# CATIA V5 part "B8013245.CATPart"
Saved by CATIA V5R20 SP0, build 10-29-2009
Part number: B8013245
Revision: 8
Definition: design
Nomenclature: B8013245
Source: made
Description: NOT SPECIFIED
Bounding box of the stored display mesh (mm): x -28 to 28, y -28 to 28, z 0 to 45
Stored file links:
  C:\Users\Utente\Desktop\3D files B801\B8013245.CATPart
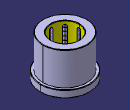
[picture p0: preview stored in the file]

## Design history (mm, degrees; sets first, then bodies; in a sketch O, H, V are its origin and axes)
Body1 "MANIFOLD_SOLID_BREP #38" (main body)
  Solid1: solid without history
Body2 "MANIFOLD_SOLID_BREP #76"
  Solid2: solid without history
Body3 "MANIFOLD_SOLID_BREP #114"
  Solid3: solid without history
Body4 "MANIFOLD_SOLID_BREP #152"
  Solid4: solid without history
Body5 "MANIFOLD_SOLID_BREP #190"
  Solid5: solid without history
Body6 "MANIFOLD_SOLID_BREP #228"
  Solid6: solid without history
Body7 "MANIFOLD_SOLID_BREP #266"
  Solid7: solid without history
Body8 "MANIFOLD_SOLID_BREP #304"
  Solid8: solid without history
Body9 "MANIFOLD_SOLID_BREP #342"
  Solid9: solid without history
Body10 "MANIFOLD_SOLID_BREP #2292"
  Solid10: solid without history
Body11 "MANIFOLD_SOLID_BREP #2330"
  Solid11: solid without history
Body12 "MANIFOLD_SOLID_BREP #2368"
  Solid12: solid without history
Body13 "MANIFOLD_SOLID_BREP #2406"
  Solid13: solid without history
Body14 "MANIFOLD_SOLID_BREP #2444"
  Solid14: solid without history
Body15 "MANIFOLD_SOLID_BREP #2482"
  Solid15: solid without history
Body16 "MANIFOLD_SOLID_BREP #2520"
  Solid16: solid without history
Body17 "MANIFOLD_SOLID_BREP #2558"
  Solid17: solid without history
Body18 "MANIFOLD_SOLID_BREP #2596"
  Solid18: solid without history
Body19 "MANIFOLD_SOLID_BREP #2634"
  Solid19: solid without history
Body20 "MANIFOLD_SOLID_BREP #2672"
  Solid20: solid without history
Body21 "MANIFOLD_SOLID_BREP #2710"
  Solid21: solid without history
Body22 "MANIFOLD_SOLID_BREP #2748"
  Solid22: solid without history
Body23 "MANIFOLD_SOLID_BREP #2786"
  Solid23: solid without history
Body24 "MANIFOLD_SOLID_BREP #2824"
  Solid24: solid without history
Body25 "MANIFOLD_SOLID_BREP #2862"
  Solid25: solid without history
Body26 "MANIFOLD_SOLID_BREP #2900"
  Solid26: solid without history
Body27 "MANIFOLD_SOLID_BREP #2938"
  Solid27: solid without history
Body28 "MANIFOLD_SOLID_BREP #2976"
  Solid28: solid without history
Body29 "MANIFOLD_SOLID_BREP #3014"
  Solid29: solid without history
Body30 "MANIFOLD_SOLID_BREP #3052"
  Solid30: solid without history
Body31 "MANIFOLD_SOLID_BREP #3090"
  Solid31: solid without history
Body32 "MANIFOLD_SOLID_BREP #3128"
  Solid32: solid without history
Body33 "MANIFOLD_SOLID_BREP #3166"
  Solid33: solid without history
Body34 "MANIFOLD_SOLID_BREP #3204"
  Solid34: solid without history
Body35 "MANIFOLD_SOLID_BREP #3242"
  Solid35: solid without history
Body36 "MANIFOLD_SOLID_BREP #3280"
  Solid36: solid without history
Body37 "MANIFOLD_SOLID_BREP #3318"
  Solid37: solid without history
Body38 "MANIFOLD_SOLID_BREP #3356"
  Solid38: solid without history
Body39 "MANIFOLD_SOLID_BREP #3394"
  Solid39: solid without history
Body40 "MANIFOLD_SOLID_BREP #3432"
  Solid40: solid without history
Body41 "MANIFOLD_SOLID_BREP #3470"
  Solid41: solid without history
Body42 "MANIFOLD_SOLID_BREP #3508"
  Solid42: solid without history
Body43 "MANIFOLD_SOLID_BREP #3546"
  Solid43: solid without history
Body44 "MANIFOLD_SOLID_BREP #3584"
  Solid44: solid without history
Body45 "MANIFOLD_SOLID_BREP #3622"
  Solid45: solid without history
Body46 "MANIFOLD_SOLID_BREP #3660"
  Solid46: solid without history
Body47 "MANIFOLD_SOLID_BREP #3698"
  Solid47: solid without history
Body48 "MANIFOLD_SOLID_BREP #3736"
  Solid48: solid without history
Body49 "MANIFOLD_SOLID_BREP #3774"
  Solid49: solid without history
Body50 "MANIFOLD_SOLID_BREP #3812"
  Solid50: solid without history
Body51 "MANIFOLD_SOLID_BREP #3850"
  Solid51: solid without history
Body52 "MANIFOLD_SOLID_BREP #3888"
  Solid52: solid without history
Body53 "MANIFOLD_SOLID_BREP #3926"
  Solid53: solid without history
Body54 "MANIFOLD_SOLID_BREP #3964"
  Solid54: solid without history
Body55 "MANIFOLD_SOLID_BREP #4002"
  Solid55: solid without history
Body56 "MANIFOLD_SOLID_BREP #4040"
  Solid56: solid without history
Body57 "MANIFOLD_SOLID_BREP #4078"
  Solid57: solid without history
Body58 "MANIFOLD_SOLID_BREP #4116"
  Solid58: solid without history
Body59 "MANIFOLD_SOLID_BREP #4154"
  Solid59: solid without history
Body60 "MANIFOLD_SOLID_BREP #4192"
  Solid60: solid without history
Body61 "MANIFOLD_SOLID_BREP #4230"
  Solid61: solid without history
Body62 "MANIFOLD_SOLID_BREP #4268"
  Solid62: solid without history
Body63 "MANIFOLD_SOLID_BREP #4306"
  Solid63: solid without history
Body64 "MANIFOLD_SOLID_BREP #4344"
  Solid64: solid without history
Body65 "MANIFOLD_SOLID_BREP #4382"
  Solid65: solid without history
Body66 "MANIFOLD_SOLID_BREP #4420"
  Solid66: solid without history
Body67 "MANIFOLD_SOLID_BREP #4458"
  Solid67: solid without history
Body68 "MANIFOLD_SOLID_BREP #4496"
  Solid68: solid without history
Body69 "MANIFOLD_SOLID_BREP #4534"
  Solid69: solid without history
Body70 "MANIFOLD_SOLID_BREP #4572"
  Solid70: solid without history
Body71 "MANIFOLD_SOLID_BREP #4610"
  Solid71: solid without history
Body72 "MANIFOLD_SOLID_BREP #4648"
  Solid72: solid without history
Body73 "MANIFOLD_SOLID_BREP #4686"
  Solid73: solid without history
